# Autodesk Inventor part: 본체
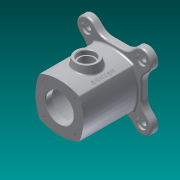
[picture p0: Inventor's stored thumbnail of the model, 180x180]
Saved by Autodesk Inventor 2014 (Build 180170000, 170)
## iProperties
Created: 2016-05
Part Number: 본체
Material: 알루미늄 6061
Document SubType Name: Modeling
Designer: Administrator
Density: 2.71 g/cm^3
Appearance: 알루미늄 - 평지
Mass: 1113.81 g
Surface Area: 865.194 cm^2
Volume: 411.001 cm^3
Author: Administrator
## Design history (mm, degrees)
sketch "스케치2" dims "d0" = 100
  geometry: L1 (35.355, -35.355)-(-35.355, -35.355); L2 (-35.355, -35.355)-(-35.355, 35.355); L3 (-35.355, 35.355)-(35.355, 35.355); L4 (35.355, 35.355)-(35.355, -35.355); L5 (35.355, -35.355)-(-35.355, 35.355); L6 (-35.355, -35.355)-(35.355, 35.355); A1 r 85.579 centre (-42.579, 0) between (35.355, -35.355) and (35.355, 35.355); A2 r 85.579 centre (42.579, 0) between (-35.355, 35.355) and (-35.355, -35.355); A3 r 85.579 centre (0, -42.579) between (35.355, 35.355) and (-35.355, 35.355); A4 r 85.579 centre (0, 42.579) between (-35.355, -35.355) and (35.355, -35.355); 2 further points
  constraints: 12 end point, 8 point on circle, 4 centre point, 3 equal radius, 2 midpoint, 2 parallel, 2 perpendicular, 1 coincident, 1 horizontal, 3 other
  dimensions: "d1" = 86 dimension on A2 A1; "d2" = 86 dimension on A4 A3 (derived)
extrude "돌출1" new body sketch "스케치2" distance "d3" = 61; taper "d5" = 0 deg; dims "d4" = 49, "d6" = 0
sketch "스케치3"
  geometry: L1 (-49, 0)-(-37, 0); L2 (-37, 0)-(-37, 25); L3 (-37, 25)-(-49, 25); L4 (-49, 25)-(-49, 0); L5 (-37, 0)-(49, 0); L6 (49, 0)-(49, 35); L7 (49, 35)-(-37, 35); L8 (-37, 35)-(-37, 0); L9 (49, 0)-(61, 0); L10 (61, 0)-(61, 25); L11 (61, 25)-(49, 25); L12 (49, 25)-(49, 0); L13 (-49, 35.355)-(-49, -35.355) reference; L14 (61, -35.355)-(61, 35.355) reference; L15 (-71, 0)-(83, 0) reference; 1 further point
  constraints: 24 end point, 6 parallel, 3 horizontal, 3 perpendicular, 2 midpoint
  dimensions: "d7" = 70 diameter of L7 L5; "d8" = 50 diameter of L11 L5; "d9" = 50 diameter of L3 L5; "d10" = 12 distance between parallel lines of L4 L2; "d11" = 12 distance between parallel lines of L14 L6; "d12" = 86 distance between parallel lines of L12 L2 (derived)
revolve "회전1" sketch "스케치3" stored, may be unused: angle "d13" = 90 deg
sketch "스케치4" dims "d15" = 70
  geometry: L1 (-98, 0)-(98, 0) reference; L2 (49.497, -49.497)-(0, 0); L3 (41.485, -16.03)-(16.03, -41.485); L4 (36.77, -62.225)-(16.03, -41.485); L5 (62.225, -36.77)-(41.485, -16.03); A1 r 18 centre (49.497, -49.497) between (36.77, -62.225) and (62.225, -36.77); A2 r 85.579 centre (-42.579, 0) between (35.355, -35.355) and (35.355, 35.355) reference; A3 r 85.579 centre (0, 42.579) between (-35.355, -35.355) and (35.355, -35.355) reference; 1 further point
  constraints: 8 end point, 4 point on circle, 2 parallel, 2 tangent, 1 centre point, 1 coincident, 3 other
  dimensions: "d17" = 45 deg angle of L1 L2; "d21" = 18 radius of A1; "d95" = 36 distance between parallel lines of L4 L5 (derived)
extrude "돌출2" join sketch "스케치4" distance "d18" = 12; taper "d19" = 0 deg
sketch "스케치7"
  geometry: L1 (49, 49)-(-49, 49); L2 (-49, 49)-(-49, -49); L3 (-49, -49)-(49, -49); L4 (49, -49)-(49, 49); L5 (49, 49)-(-49, -49); L6 (-49, 49)-(49, -49); L7 (62.225, -36.77)-(41.485, -16.03) reference; L8 (16.03, -41.485)-(36.77, -62.225) reference; A1 r 85.579 centre (42.579, 0) between (-35.355, 35.355) and (-35.355, -35.355) reference; A2 r 85.579 centre (0, -42.579) between (35.355, 35.355) and (-35.355, 35.355) reference; A3 r 85.579 centre (0, 42.579) between (-35.355, -35.355) and (16.03, -41.485) reference; A4 r 85.579 centre (-42.579, 0) between (41.485, -16.03) and (35.355, 35.355) reference; 3 further points
  constraints: 12 end point, 4 point on line, 2 midpoint, 2 parallel, 2 perpendicular, 1 horizontal
  dimensions: "d58" = 98 distance of L1.start L1.end
extrude "돌출4" join sketch "스케치7" distance "d59" = 12; taper "d60" = 0 deg
hole "구멍1" diameter "d24" = 10; stored, may be unused: countersink angle "d28" = 90 deg, drill point angle "d30" = 0 deg; dims "d22" = 10, "d23" = 10, "d25" = 6, "d26" = 18, "d27" = 4, "d29" = 8
sketch "스케치5" dims "d34" = 40
  geometry: L1 (0, 0)-(28.284, -28.284); L2 (-98, 0)-(98, 0) reference; 1 further point
  constraints: 2 end point, 1 coincident, 3 other
  dimensions: "d32" = 45 deg angle of L2 L1 (= d17)
hole "구멍2" sketch "스케치5" at (28.284, -28.284) diameter "d35" = 3.242; stored, may be unused: countersink angle "d39" = 90 deg, drill point angle "d41" = 118 deg; dims "d36" = 7, "d37" = 18, "d38" = 4, "d40" = 10
node "작업 평면1"
sketch "스케치6"
  geometry: C1 r 20 at (0, 0); 1 further point
  constraints: 1 centre point, 1 coincident
  dimensions: "d46" = 40 diameter of C1
extrude "돌출3" join sketch "스케치6" stored distance "d47" = 12; taper "d48" = 10 deg
hole "구멍3" diameter "d51" = 25; stored, may be unused: countersink angle "d55" = 90 deg, drill point angle "d57" = 0 deg; dims "d49" = 10, "d50" = 10, "d52" = 7, "d53" = 30, "d54" = 8, "d56" = 10
fillet "모깎기1" dims "d61" = 25
fillet "모깎기2" dims "d62" = 3
fillet "모깎기3" dims "d63" = 3
fillet "모깎기5" dims "d65" = 3
fillet "모깎기6" dims "d66" = 3
chamfer "모따기1" distance "d67" = 1; stored, may be unused: second distance "d68" = 2, angle "d69" = 45 deg
chamfer "모따기2" distance "d70" = 1; stored, may be unused: second distance "d71" = 2, angle "d72" = 45 deg
chamfer "모따기3" distance "d73" = 1; stored, may be unused: second distance "d74" = 2, angle "d75" = 45 deg
sketch "스케치8" dims "d76" = 40
  geometry: L1 (0, 0)-(-28.284, 28.284); L2 (-94.496, 0)-(94.496, 0) reference; 1 further point
  constraints: 2 end point, 1 coincident, 3 other
  dimensions: "d77" = 45 deg angle of L1 L2
hole "구멍4" sketch "스케치8" at (-28.284, 28.284) diameter "d78" = 3.242; stored, may be unused: countersink angle "d82" = 90 deg, drill point angle "d84" = 118 deg; dims "d79" = 7, "d80" = 19.05, "d81" = 4.775, "d83" = 10
sketch "스케치10"
  geometry: L1 (-34.285, -49)-(34.285, -49) reference; 2 further points
  constraints: 1 other
  dimensions: "d90" = 49 distance from line of L1 point (29, 0); "d91" = 29 distance of point (29, 0) point (0, 0)
feature "엠보싱1" sketch "스케치10" dims "d0" = 100, "d1" = 86, "d2" = 86 (derived), "d7" = 70, "d8" = 50, "d9" = 50, "d10" = 12, "d11" = 12, "d12" = 86 (derived), "d92" = 0.5, "d93" = 0
fillet "모깎기7" dims "d94" = 3
node "솔리드1"
pattern_circular "원형 패턴1" dims "d43" = 360 deg
pattern_circular "원형 패턴2" dims angle "d86" = 360 deg
other parameters: "d45" = 55
